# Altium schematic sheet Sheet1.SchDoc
size Letter
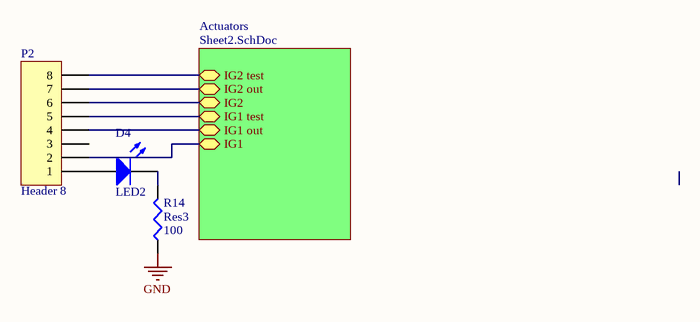
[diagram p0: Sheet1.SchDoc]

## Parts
D4  LED2  [3.2X1.6X1.1]
P2  Header 8  [HDR1X8]
R14  Res3  value 100  [J1-0603]

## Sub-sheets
Actuators = Sheet2.SchDoc: IG1 out (bidir), IG1 test (bidir), IG2 (bidir), IG2 test (bidir), IG2 out (bidir), IG1 (bidir)

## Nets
GND: R14.1
NetD4_1: D4.1(A) P2.1
NetD4_2: D4.2(K) R14.2
NetP2_2: P2.2 ; sheet Actuators/IG1
NetP2_4: P2.4 ; sheet Actuators/IG1 out
NetP2_5: P2.5 ; sheet Actuators/IG1 test
NetP2_6: P2.6 ; sheet Actuators/IG2
NetP2_7: P2.7 ; sheet Actuators/IG2 out
NetP2_8: P2.8 ; sheet Actuators/IG2 test

Not connected (* = marked no-connect by the designer): P2 3

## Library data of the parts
D4 = LED2: Typical RED, GREEN, YELLOW, AMBER GaAs LED
P2 = Header 8: Header, 8-Pin
R14 = Res3: Resistor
